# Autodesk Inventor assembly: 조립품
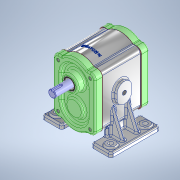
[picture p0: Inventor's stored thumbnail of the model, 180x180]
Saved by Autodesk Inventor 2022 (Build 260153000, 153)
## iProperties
Created: 2023-06
Part Number: 조립품
Document SubType Name: Assembly
Designer: PC-03
Author: PC-03
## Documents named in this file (12)
- C:\Users\PC-03\Desktop\730606V1006\조립품.iam
- C:\Users\PC-03\Desktop\730606V1006\본체.ipt
- C:\Users\PC-03\Desktop\730606V1006\가스켓.ipt
- C:\Users\PC-03\Desktop\730606V1006\뒷커버.ipt
- C:\Users\PC-03\Desktop\730606V1006\니들베어링 NA 4902.ipt
- C:\Users\PC-03\Desktop\730606V1006\앞커버.ipt
- C:\Users\PC-03\Desktop\730606V1006\샤프트.ipt
- C:\Users\PC-03\Desktop\730606V1006\묻힘키 6x6x40.ipt
- C:\Users\PC-03\Desktop\730606V1006\메인 드라이브 기어.ipt
- C:\Users\PC-03\Desktop\730606V1006\서브 드라이브 기어.ipt
- C:\Users\PC-03\Desktop\730606V1006\오일실 15 25 7.ipt
- C:\Users\PC-03\Desktop\730606V1006\육각 소켓 머리 볼트 M8 x 100.ipt
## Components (2 placed, 1 different names)
1. 가스켓:1
2. 가스켓:2
